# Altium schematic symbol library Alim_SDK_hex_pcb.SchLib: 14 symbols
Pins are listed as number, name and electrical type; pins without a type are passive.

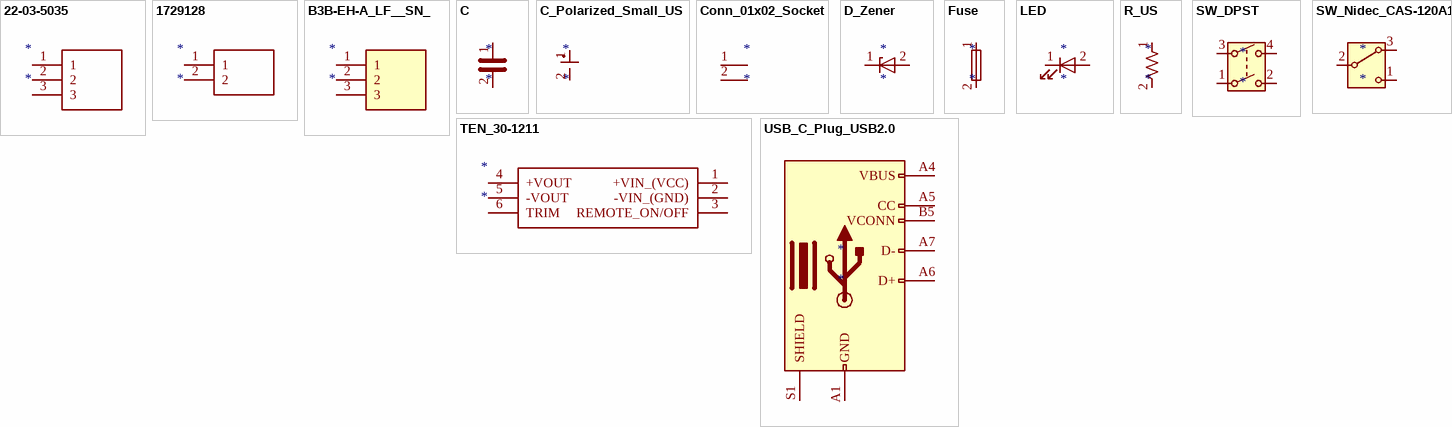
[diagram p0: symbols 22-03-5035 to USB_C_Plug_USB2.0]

## 22-03-5035
designator *
pins: 1, 2, 3

## 1729128
designator *
pins: 1, 2

## B3B-EH-A_LF__SN_
designator *
pins: 1, 2, 3

## C
designator *
pins: 1, 2

## C_Polarized_Small_US
designator *
pins: 1, 2

## Conn_01x02_Socket
designator *
pins: 1 Pin_1, 2 Pin_2

## D_Zener
designator *
pins: 1 K, 2 A

## Fuse
designator *
pins: 1, 2

## LED
designator *
pins: 1 K, 2 A

## R_US
designator *
pins: 1, 2

## SW_DPST
designator *
pins: 1, 2, 3, 4

## SW_Nidec_CAS-120A1
designator *
pins: 1 C, 2 B, 3 A

## TEN_30-1211
designator *
pins: 1 +VIN_(VCC), 2 -VIN_(GND), 3 REMOTE_ON/OFF, 4 +VOUT, 5 -VOUT, 6 TRIM

## USB_C_Plug_USB2.0
designator *
pins: A1 GND, A4 VBUS, A5 CC, A6 D+, A7 D-, A9 VBUS hidden, A12 GND hidden, B1 GND hidden, B4 VBUS hidden, B5 VCONN, B9 VBUS hidden, B12 GND hidden, S1 SHIELD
